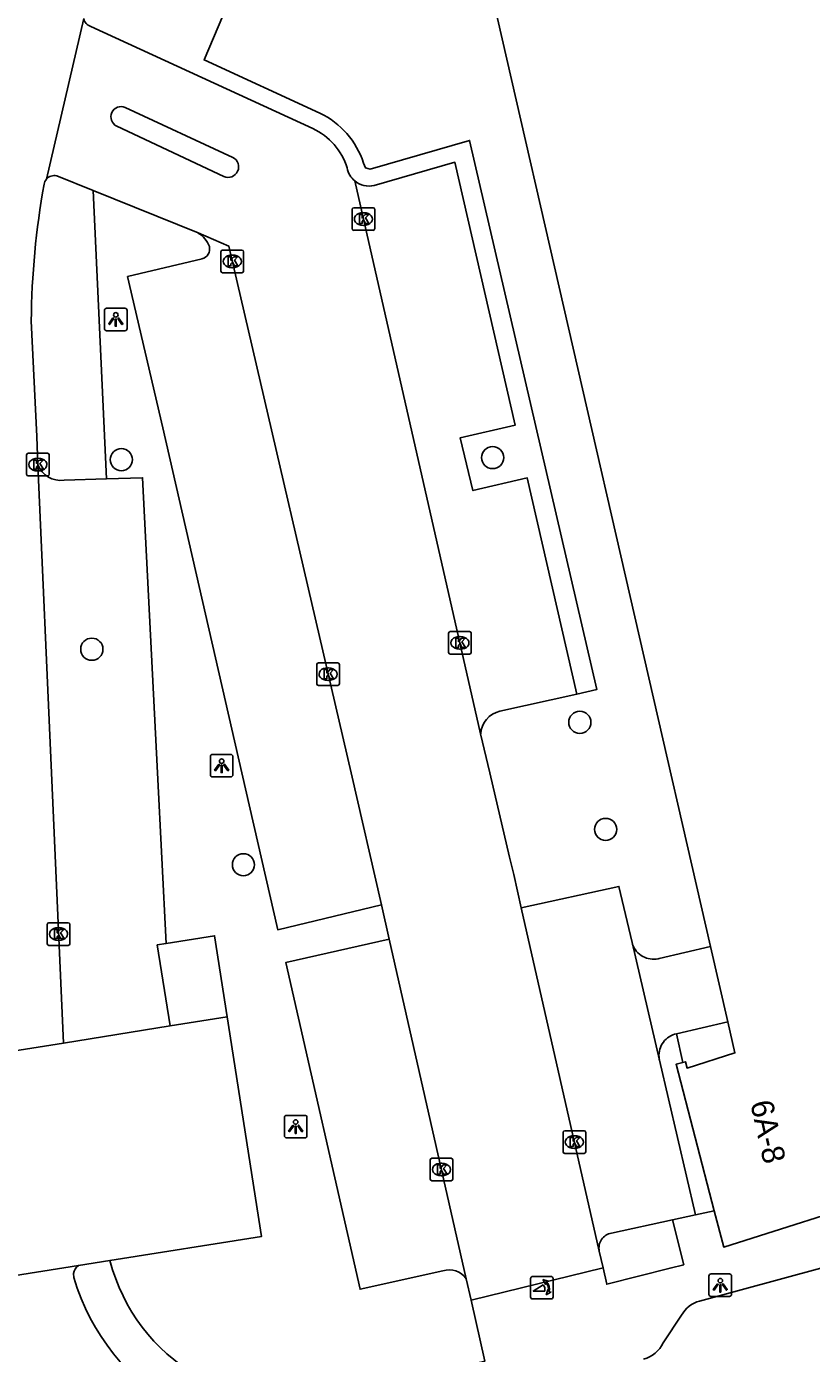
# Model space of a CAD drawing. Extents: x 160676 to 161153, y 383244 to 383713.
# Drawn here: x 160707.5 to 160742.2, y 383474.3 to 383533 of the extents above; entities that cross this region are included whole.
import ezdxf

# ---------------------------------------------------------------- set-up
doc = ezdxf.new("R2010")
doc.units = 0
for name, color, linetype in [('IMGEO_Boom', 7, 'Continuous'), ('IMGEO_Groenvoorziening', 7, 'Continuous'), ('IMGEO_Kolk', 7, 'Continuous'), ('IMGEO_Lichtpunt', 7, 'Continuous'), ('IMGEO_Pand', 7, 'Continuous'), ('IMGEO_Pand_nummerreeks', 7, 'Continuous'), ('IMGEO_Parkeervlak_open', 7, 'Continuous'), ('IMGEO_Poller', 7, 'Continuous'), ('IMGEO_Rijbaan_lokaal_open', 7, 'Continuous'), ('IMGEO_Voetpad_open', 7, 'Continuous')]:
    doc.layers.add(name, color=color, linetype=linetype)

msp = doc.modelspace()

# ---------------------------------------------------------------- linework, layer by layer
at = {"layer": 'IMGEO_Boom'}
for centre in [(160728.093, 383513.938), (160711.694, 383513.847), (160710.389, 383505.471), (160731.946, 383502.238), (160733.084, 383497.505), (160717.086, 383495.944)]:
    msp.add_circle(centre, 0.489, dxfattribs=at)
at = {"layer": 'IMGEO_Groenvoorziening'}
msp.add_lwpolyline([(160711.04, 383512.996), (160710.451, 383525.74)], dxfattribs=at)
at = {"layer": 'IMGEO_Kolk'}
for p, q in [((160721.96, 383524.981), (160722.812, 383524.981)), ((160721.885, 383524.055), (160721.885, 383524.907)), ((160722.373, 383524.761), (160722.398, 383524.761)), ((160722.886, 383524.907), (160722.886, 383524.055)), ((160722.812, 383523.981), (160721.96, 383523.981)), ((160722.396, 383524.201), (160722.371, 383524.201)), ((160716.092, 383522.182), (160716.092, 383523.034)), ((160716.167, 383523.108), (160717.019, 383523.108)), ((160716.58, 383522.888), (160716.605, 383522.888)), ((160717.093, 383523.034), (160717.093, 383522.182)), ((160717.019, 383522.108), (160716.167, 383522.108)), ((160716.603, 383522.328), (160716.578, 383522.328)), ((160707.505, 383513.202), (160707.505, 383514.054)), ((160707.58, 383514.128), (160708.432, 383514.128)), ((160707.993, 383513.908), (160708.018, 383513.908)), ((160708.506, 383514.054), (160708.506, 383513.202)), ((160708.016, 383513.348), (160707.991, 383513.348)), ((160708.432, 383513.128), (160707.58, 383513.128)), ((160726.222, 383506.251), (160727.074, 383506.251)), ((160726.147, 383505.325), (160726.147, 383506.177)), ((160726.635, 383506.031), (160726.66, 383506.031)), ((160727.148, 383506.177), (160727.148, 383505.325)), ((160727.074, 383505.251), (160726.222, 383505.251)), ((160726.658, 383505.471), (160726.633, 383505.471)), ((160720.326, 383503.941), (160720.326, 383504.793)), ((160720.401, 383504.867), (160721.253, 383504.867)), ((160720.814, 383504.647), (160720.839, 383504.647)), ((160721.327, 383504.793), (160721.327, 383503.941)), ((160721.253, 383503.867), (160720.401, 383503.867)), ((160720.837, 383504.087), (160720.812, 383504.087)), ((160708.418, 383492.454), (160708.418, 383493.306)), ((160708.493, 383493.38), (160709.345, 383493.38)), ((160709.419, 383493.306), (160709.419, 383492.454)), ((160708.906, 383493.16), (160708.931, 383493.16)), ((160709.345, 383492.38), (160708.493, 383492.38)), ((160708.929, 383492.6), (160708.904, 383492.6)), ((160731.204, 383483.263), (160731.204, 383484.115)), ((160731.279, 383484.189), (160732.131, 383484.189)), ((160731.692, 383483.969), (160731.717, 383483.969)), ((160732.205, 383484.115), (160732.205, 383483.263)), ((160731.715, 383483.409), (160731.69, 383483.409)), ((160725.334, 383482.051), (160725.334, 383482.903)), ((160725.409, 383482.977), (160726.261, 383482.977)), ((160725.822, 383482.757), (160725.847, 383482.757)), ((160726.335, 383482.903), (160726.335, 383482.051)), ((160732.131, 383483.189), (160731.279, 383483.189)), ((160725.845, 383482.197), (160725.82, 383482.197)), ((160726.261, 383481.977), (160725.409, 383481.977))]:
    msp.add_line(p, q, dxfattribs=at)
for points in [[(160721.96, 383524.981), (160722.812, 383524.981)], [(160721.885, 383524.055), (160721.885, 383524.907)], [(160722.206, 383524.681), (160722.329, 383524.681), (160722.329, 383524.53), (160722.459, 383524.681), (160722.623, 383524.681), (160722.477, 383524.53), (160722.63, 383524.281), (160722.478, 383524.281), (160722.393, 383524.445), (160722.329, 383524.378), (160722.329, 383524.281), (160722.206, 383524.281), (160722.206, 383524.681)], [(160722.886, 383524.907), (160722.886, 383524.055)], [(160722.812, 383523.981), (160721.96, 383523.981)], [(160716.092, 383522.182), (160716.092, 383523.034)], [(160716.167, 383523.108), (160717.019, 383523.108)], [(160716.413, 383522.808), (160716.536, 383522.808), (160716.536, 383522.657), (160716.666, 383522.808), (160716.83, 383522.808), (160716.684, 383522.657), (160716.837, 383522.408), (160716.685, 383522.408), (160716.6, 383522.572), (160716.536, 383522.505), (160716.536, 383522.408), (160716.413, 383522.408), (160716.413, 383522.808)], [(160717.093, 383523.034), (160717.093, 383522.182)], [(160717.019, 383522.108), (160716.167, 383522.108)], [(160707.505, 383513.202), (160707.505, 383514.054)], [(160707.58, 383514.128), (160708.432, 383514.128)], [(160707.826, 383513.828), (160707.949, 383513.828), (160707.949, 383513.677), (160708.079, 383513.828), (160708.243, 383513.828), (160708.097, 383513.677), (160708.25, 383513.428), (160708.098, 383513.428), (160708.013, 383513.592), (160707.949, 383513.525), (160707.949, 383513.428), (160707.826, 383513.428), (160707.826, 383513.828)], [(160708.506, 383514.054), (160708.506, 383513.202)], [(160708.432, 383513.128), (160707.58, 383513.128)], [(160726.222, 383506.251), (160727.074, 383506.251)], [(160726.147, 383505.325), (160726.147, 383506.177)], [(160726.468, 383505.951), (160726.591, 383505.951), (160726.591, 383505.8), (160726.721, 383505.951), (160726.885, 383505.951), (160726.739, 383505.8), (160726.892, 383505.551), (160726.74, 383505.551), (160726.655, 383505.715), (160726.591, 383505.648), (160726.591, 383505.551), (160726.468, 383505.551), (160726.468, 383505.951)], [(160727.148, 383506.177), (160727.148, 383505.325)], [(160727.074, 383505.251), (160726.222, 383505.251)], [(160720.326, 383503.941), (160720.326, 383504.793)], [(160720.401, 383504.867), (160721.253, 383504.867)], [(160720.647, 383504.567), (160720.77, 383504.567), (160720.77, 383504.416), (160720.9, 383504.567), (160721.064, 383504.567), (160720.918, 383504.416), (160721.071, 383504.167), (160720.919, 383504.167), (160720.834, 383504.331), (160720.77, 383504.264), (160720.77, 383504.167), (160720.647, 383504.167), (160720.647, 383504.567)], [(160721.327, 383504.793), (160721.327, 383503.941)], [(160721.253, 383503.867), (160720.401, 383503.867)], [(160708.418, 383492.454), (160708.418, 383493.306)], [(160708.493, 383493.38), (160709.345, 383493.38)], [(160709.419, 383493.306), (160709.419, 383492.454)], [(160708.739, 383493.08), (160708.862, 383493.08), (160708.862, 383492.929), (160708.992, 383493.08), (160709.156, 383493.08), (160709.01, 383492.929), (160709.163, 383492.68), (160709.011, 383492.68), (160708.926, 383492.844), (160708.862, 383492.777), (160708.862, 383492.68), (160708.739, 383492.68), (160708.739, 383493.08)], [(160709.345, 383492.38), (160708.493, 383492.38)], [(160731.204, 383483.263), (160731.204, 383484.115)], [(160731.279, 383484.189), (160732.131, 383484.189)], [(160732.205, 383484.115), (160732.205, 383483.263)], [(160731.525, 383483.889), (160731.648, 383483.889), (160731.648, 383483.738), (160731.778, 383483.889), (160731.942, 383483.889), (160731.796, 383483.738), (160731.949, 383483.489), (160731.797, 383483.489), (160731.712, 383483.653), (160731.648, 383483.586), (160731.648, 383483.489), (160731.525, 383483.489), (160731.525, 383483.889)], [(160725.334, 383482.051), (160725.334, 383482.903)], [(160725.409, 383482.977), (160726.261, 383482.977)], [(160726.335, 383482.903), (160726.335, 383482.051)], [(160732.131, 383483.189), (160731.279, 383483.189)], [(160725.655, 383482.677), (160725.778, 383482.677), (160725.778, 383482.526), (160725.908, 383482.677), (160726.072, 383482.677), (160725.926, 383482.526), (160726.079, 383482.277), (160725.927, 383482.277), (160725.842, 383482.441), (160725.778, 383482.374), (160725.778, 383482.277), (160725.655, 383482.277), (160725.655, 383482.677)], [(160726.261, 383481.977), (160725.409, 383481.977)]]:
    msp.add_lwpolyline(points, dxfattribs=at)
for centre, start, end in [((160721.962, 383524.905), 91.55205, 178.44795), ((160721.962, 383524.905), 91.55205, 178.44795), ((160722.81, 383524.905), 1.55205, 88.44795), ((160722.81, 383524.905), 1.55205, 88.44795), ((160721.962, 383524.057), 181.55205, 268.44795), ((160721.962, 383524.057), 181.55205, 268.44795), ((160722.81, 383524.057), 271.55205, 358.44795), ((160722.81, 383524.057), 271.55205, 358.44795), ((160716.169, 383523.032), 91.55205, 178.44795), ((160716.169, 383523.032), 91.55205, 178.44795), ((160717.017, 383523.032), 1.55205, 88.44795), ((160717.017, 383523.032), 1.55205, 88.44795), ((160716.169, 383522.184), 181.55205, 268.44795), ((160716.169, 383522.184), 181.55205, 268.44795), ((160717.017, 383522.184), 271.55205, 358.44795), ((160717.017, 383522.184), 271.55205, 358.44795), ((160707.582, 383514.052), 91.55205, 178.44795), ((160707.582, 383514.052), 91.55205, 178.44795), ((160708.43, 383514.052), 1.55205, 88.44795), ((160708.43, 383514.052), 1.55205, 88.44795), ((160707.582, 383513.204), 181.55205, 268.44795), ((160707.582, 383513.204), 181.55205, 268.44795), ((160708.43, 383513.204), 271.55205, 358.44795), ((160708.43, 383513.204), 271.55205, 358.44795), ((160726.224, 383506.175), 91.55205, 178.44795), ((160726.224, 383506.175), 91.55205, 178.44795), ((160727.072, 383506.175), 1.55205, 88.44795), ((160727.072, 383506.175), 1.55205, 88.44795), ((160726.224, 383505.327), 181.55205, 268.44795), ((160726.224, 383505.327), 181.55205, 268.44795), ((160727.072, 383505.327), 271.55205, 358.44795), ((160727.072, 383505.327), 271.55205, 358.44795), ((160720.403, 383504.791), 91.55205, 178.44795), ((160720.403, 383504.791), 91.55205, 178.44795), ((160721.251, 383504.791), 1.55205, 88.44795), ((160721.251, 383504.791), 1.55205, 88.44795), ((160720.403, 383503.943), 181.55205, 268.44795), ((160720.403, 383503.943), 181.55205, 268.44795), ((160721.251, 383503.943), 271.55205, 358.44795), ((160721.251, 383503.943), 271.55205, 358.44795), ((160708.495, 383493.304), 91.55205, 178.44795), ((160708.495, 383493.304), 91.55205, 178.44795), ((160709.343, 383493.304), 1.55205, 88.44795), ((160709.343, 383493.304), 1.55205, 88.44795), ((160708.495, 383492.456), 181.55205, 268.44795), ((160708.495, 383492.456), 181.55205, 268.44795), ((160709.343, 383492.456), 271.55205, 358.44795), ((160709.343, 383492.456), 271.55205, 358.44795), ((160731.281, 383484.113), 91.55205, 178.44795), ((160731.281, 383484.113), 91.55205, 178.44795), ((160732.129, 383484.113), 1.55205, 88.44795), ((160732.129, 383484.113), 1.55205, 88.44795), ((160725.411, 383482.901), 91.55205, 178.44795), ((160725.411, 383482.901), 91.55205, 178.44795), ((160726.259, 383482.901), 1.55205, 88.44795), ((160726.259, 383482.901), 1.55205, 88.44795), ((160731.281, 383483.265), 181.55205, 268.44795), ((160731.281, 383483.265), 181.55205, 268.44795), ((160732.129, 383483.265), 271.55205, 358.44795), ((160732.129, 383483.265), 271.55205, 358.44795), ((160725.411, 383482.053), 181.55205, 268.44795), ((160725.411, 383482.053), 181.55205, 268.44795), ((160726.259, 383482.053), 271.55205, 358.44795), ((160726.259, 383482.053), 271.55205, 358.44795)]:
    msp.add_arc(centre, 0.0765, start, end, dxfattribs=at)
for centre, major_axis, ratio, start_param, end_param in [((160722.372, 383524.481), (-0.387, 0.002), 0.722429, 4.712389, 7.853982), ((160722.397, 383524.481), (-0.39, 0.002), 0.717154, 1.570796, 4.712389), ((160716.579, 383522.608), (-0.387, 0.002), 0.722429, 4.712389, 7.853982), ((160716.604, 383522.608), (-0.39, 0.002), 0.717154, 1.570796, 4.712389), ((160707.992, 383513.628), (-0.387, 0.002), 0.722429, 4.712389, 7.853982), ((160708.017, 383513.628), (-0.39, 0.002), 0.717154, 1.570796, 4.712389), ((160726.634, 383505.751), (-0.387, 0.002), 0.722429, 4.712389, 7.853982), ((160726.659, 383505.751), (-0.39, 0.002), 0.717154, 1.570796, 4.712389), ((160720.813, 383504.367), (-0.387, 0.002), 0.722429, 4.712389, 7.853982), ((160720.838, 383504.367), (-0.39, 0.002), 0.717154, 1.570796, 4.712389), ((160708.905, 383492.88), (-0.387, 0.002), 0.722429, 4.712389, 7.853982), ((160708.93, 383492.88), (-0.39, 0.002), 0.717154, 1.570796, 4.712389), ((160731.691, 383483.689), (-0.387, 0.002), 0.722429, 4.712389, 7.853982), ((160731.716, 383483.689), (-0.39, 0.002), 0.717154, 1.570796, 4.712389), ((160725.821, 383482.477), (-0.387, 0.002), 0.722429, 4.712389, 7.853982), ((160725.846, 383482.477), (-0.39, 0.002), 0.717154, 1.570796, 4.712389)]:
    msp.add_ellipse(centre, major_axis=major_axis, ratio=ratio, start_param=start_param, end_param=end_param, dxfattribs=at)
at = {"layer": 'IMGEO_Lichtpunt'}
for p, q in [((160710.948, 383520.445), (160710.948, 383519.638)), ((160710.948, 383520.445), (160710.948, 383519.638)), ((160711.85, 383520.54), (160711.042, 383520.54)), ((160711.85, 383520.54), (160711.042, 383520.54)), ((160711.944, 383519.638), (160711.944, 383520.445)), ((160711.944, 383519.638), (160711.944, 383520.445)), ((160711.042, 383519.544), (160711.85, 383519.544)), ((160711.042, 383519.544), (160711.85, 383519.544)), ((160715.625, 383500.727), (160715.625, 383499.92)), ((160715.625, 383500.727), (160715.625, 383499.92)), ((160716.527, 383500.822), (160715.719, 383500.822)), ((160716.527, 383500.822), (160715.719, 383500.822)), ((160716.621, 383499.92), (160716.621, 383500.727)), ((160716.621, 383499.92), (160716.621, 383500.727)), ((160715.719, 383499.826), (160716.527, 383499.826)), ((160715.719, 383499.826), (160716.527, 383499.826)), ((160718.896, 383484.775), (160718.896, 383483.968)), ((160718.896, 383484.775), (160718.896, 383483.968)), ((160719.798, 383484.87), (160718.99, 383484.87)), ((160719.798, 383484.87), (160718.99, 383484.87)), ((160719.892, 383483.968), (160719.892, 383484.775)), ((160719.892, 383483.968), (160719.892, 383484.775)), ((160718.99, 383483.874), (160719.798, 383483.874)), ((160718.99, 383483.874), (160719.798, 383483.874)), ((160737.65, 383477.767), (160737.65, 383476.96)), ((160737.65, 383477.767), (160737.65, 383476.96)), ((160738.552, 383477.862), (160737.744, 383477.862)), ((160738.552, 383477.862), (160737.744, 383477.862)), ((160738.646, 383476.96), (160738.646, 383477.767)), ((160738.646, 383476.96), (160738.646, 383477.767)), ((160737.744, 383476.866), (160738.552, 383476.866)), ((160737.744, 383476.866), (160738.552, 383476.866))]:
    msp.add_line(p, q, dxfattribs=at)
for points in [[(160711.322, 383520.109), (160711.361, 383520.081), (160711.173, 383519.819), (160711.135, 383519.846), (160711.322, 383520.109)], [(160711.424, 383520.061), (160711.471, 383520.061), (160711.471, 383519.739), (160711.424, 383519.739), (160711.424, 383520.061)], [(160711.534, 383520.081), (160711.572, 383520.108), (160711.759, 383519.846), (160711.72, 383519.818), (160711.534, 383520.081)], [(160715.999, 383500.391), (160716.038, 383500.363), (160715.85, 383500.101), (160715.812, 383500.128), (160715.999, 383500.391)], [(160716.101, 383500.343), (160716.148, 383500.343), (160716.148, 383500.021), (160716.101, 383500.021), (160716.101, 383500.343)], [(160716.211, 383500.363), (160716.249, 383500.39), (160716.436, 383500.128), (160716.397, 383500.1), (160716.211, 383500.363)], [(160719.27, 383484.439), (160719.309, 383484.411), (160719.121, 383484.149), (160719.083, 383484.176), (160719.27, 383484.439)], [(160719.372, 383484.391), (160719.419, 383484.391), (160719.419, 383484.069), (160719.372, 383484.069), (160719.372, 383484.391)], [(160719.482, 383484.411), (160719.52, 383484.438), (160719.707, 383484.176), (160719.668, 383484.148), (160719.482, 383484.411)], [(160738.024, 383477.431), (160738.063, 383477.403), (160737.875, 383477.141), (160737.837, 383477.168), (160738.024, 383477.431)], [(160738.126, 383477.383), (160738.173, 383477.383), (160738.173, 383477.061), (160738.126, 383477.061), (160738.126, 383477.383)], [(160738.236, 383477.403), (160738.274, 383477.43), (160738.461, 383477.168), (160738.422, 383477.14), (160738.236, 383477.403)]]:
    msp.add_lwpolyline(points, dxfattribs=at)
for centre in [(160711.447, 383520.243), (160716.124, 383500.525), (160719.395, 383484.573), (160738.149, 383477.565)]:
    msp.add_circle(centre, 0.0994, dxfattribs=at)
for centre, start, end in [((160711.042, 383520.445), 90, 180), ((160711.042, 383520.445), 90, 180), ((160711.85, 383520.445), 0, 90), ((160711.85, 383520.445), 0, 90), ((160711.042, 383519.638), 180, 270), ((160711.042, 383519.638), 180, 270), ((160711.85, 383519.638), 270, 0), ((160711.85, 383519.638), 270, 360), ((160715.719, 383500.727), 90, 180), ((160715.719, 383500.727), 90, 180), ((160716.527, 383500.727), 0, 90), ((160716.527, 383500.727), 0, 90), ((160715.719, 383499.92), 180, 270), ((160715.719, 383499.92), 180, 270), ((160716.527, 383499.92), 270, 0), ((160716.527, 383499.92), 270, 360), ((160718.99, 383484.775), 90, 180), ((160718.99, 383484.775), 90, 180), ((160719.798, 383484.775), 0, 90), ((160719.798, 383484.775), 0, 90), ((160718.99, 383483.968), 180, 270), ((160718.99, 383483.968), 180, 270), ((160719.798, 383483.968), 270, 0), ((160719.798, 383483.968), 270, 360), ((160737.744, 383477.767), 90, 180), ((160737.744, 383477.767), 90, 180), ((160738.552, 383477.767), 0, 90), ((160738.552, 383477.767), 0, 90), ((160737.744, 383476.96), 180, 270), ((160737.744, 383476.96), 180, 270), ((160738.552, 383476.96), 270, 0), ((160738.552, 383476.96), 270, 360)]:
    msp.add_arc(centre, 0.0946, start, end, dxfattribs=at)
at = {"layer": 'IMGEO_Pand'}
for points in [[(160737.721, 383492.328), (160725.173, 383547.028)], [(160789.904, 383497.87), (160767.23, 383488.234), (160738.303, 383479.05), (160737.884, 383480.656)], [(160716.372, 383489.219), (160715.813, 383492.805), (160713.669, 383492.461)], [(160713.669, 383492.461), (160713.279, 383492.399), (160713.852, 383488.823)], [(160737.721, 383492.328), (160738.483, 383489.005)], [(160716.372, 383489.219), (160717.884, 383479.519), (160711.188, 383478.453)], [(160713.852, 383488.823), (160716.372, 383489.219)], [(160709.132, 383488.067), (160713.852, 383488.823)], [(160738.483, 383489.005), (160738.799, 383487.63), (160736.683, 383486.957), (160736.61, 383487.238), (160736.489, 383487.206)], [(160702.884, 383487.072), (160709.132, 383488.067)], [(160736.489, 383487.206), (160736.194, 383487.129), (160737.884, 383480.656)], [(160704.503, 383477.389), (160709.795, 383478.231)], [(160711.188, 383478.453), (160709.795, 383478.231)]]:
    msp.add_lwpolyline(points, dxfattribs=at)
at = {"layer": 'IMGEO_Parkeervlak_open'}
for points in [[(160723.192, 383494.173), (160718.603, 383493.071), (160717.015, 383500), (160713.519, 383515.256), (160711.968, 383521.939), (160715.256, 383522.716)], [(160709.166, 383512.934), (160711.04, 383512.996)], [(160713.669, 383492.461), (160713.289, 383500), (160712.633, 383513.049), (160711.04, 383512.996)], [(160731.814, 383503.489), (160728.417, 383502.725)], [(160729.35, 383494.038), (160733.671, 383494.988), (160734.251, 383492.503)], [(160725.9, 383478.001), (160722.239, 383477.188), (160718.953, 383491.622), (160723.529, 383492.661)], [(160733.347, 383479.665), (160736.046, 383480.255)]]:
    msp.add_lwpolyline(points, dxfattribs=at)
for centre, radius, start, end in [((160714.542, 383522.908), 1.096, 18.76188, 60.54904), ((160715.142, 383523.152), 0.451, 284.59568, 13.94174), ((160709.027, 383514.02), 1.094, 201.41347, 277.30147), ((160728.654, 383501.661), 1.09, 102.53469, 176.71632), ((160733.463, 383479.003), 0.673, 99.92649, 191.53992), ((160726.173, 383477.124), 0.918, 34.85336, 107.30876)]:
    msp.add_arc(centre, radius, start, end, dxfattribs=at)
at = {"layer": 'IMGEO_Poller'}
for p, q in [((160729.768, 383477.656), (160729.768, 383476.849)), ((160729.768, 383477.656), (160729.768, 383476.849)), ((160730.67, 383477.751), (160729.862, 383477.751)), ((160730.67, 383477.751), (160729.862, 383477.751)), ((160730.764, 383476.849), (160730.764, 383477.656)), ((160730.764, 383476.849), (160730.764, 383477.656)), ((160729.862, 383476.754), (160730.67, 383476.754)), ((160729.862, 383476.754), (160730.67, 383476.754))]:
    msp.add_line(p, q, dxfattribs=at)
for points in [[(160730.447, 383477.48), (160730.435, 383477.407), (160730.31, 383477.612)], [(160730.31, 383477.612), (160730.541, 383477.546), (160730.47, 383477.514)], [(160730.403, 383477.107), (160729.89, 383477.107), (160730.32, 383477.382)], [(160730.463, 383476.935), (160730.529, 383477.166), (160730.559, 383477.098)], [(160730.595, 383477.071), (160730.667, 383477.06), (160730.463, 383476.935)]]:
    msp.add_lwpolyline(points, dxfattribs=at)
for centre, radius, start, end in [((160729.862, 383477.656), 0.0946, 90, 180), ((160729.862, 383477.656), 0.0946, 90, 180), ((160730.089, 383477.167), 0.476, 351.75274, 41.16905), ((160730.089, 383477.167), 0.516, 349.35686, 42.29123), ((160730.67, 383477.656), 0.0946, 0, 90), ((160730.67, 383477.656), 0.0946, 0, 90), ((160730.075, 383477.157), 0.332, 351.32473, 42.4854), ((160729.862, 383476.849), 0.0946, 180, 270), ((160729.862, 383476.849), 0.0946, 180, 270), ((160730.67, 383476.849), 0.0946, 270, 0), ((160730.67, 383476.849), 0.0946, 270, 0)]:
    msp.add_arc(centre, radius, start, end, dxfattribs=at)
at = {"layer": 'IMGEO_Rijbaan_lokaal_open'}
for points in [[(160708.388, 383526.243), (160710.033, 383533.347)], [(160710.34, 383532.987), (160720.149, 383528.479)], [(160716.618, 383527.201), (160711.867, 383529.41)], [(160711.49, 383528.589), (160716.224, 383526.362)], [(160710.451, 383525.74), (160708.839, 383526.394)], [(160722.003, 383526.166), (160727.565, 383501.723)], [(160715.081, 383523.863), (160710.451, 383525.74)], [(160723.192, 383494.173), (160721.84, 383500), (160716.435, 383523.285), (160715.081, 383523.863)], [(160708.008, 383513.62), (160707.953, 383514.866), (160707.714, 383519.975)], [(160709.132, 383488.067), (160708.607, 383500), (160708.008, 383513.62)], [(160727.565, 383501.723), (160727.97, 383500), (160728.843, 383496.285), (160729.026, 383495.511), (160729.35, 383494.038)], [(160723.529, 383492.661), (160723.192, 383494.173)], [(160729.35, 383494.038), (160732.804, 383478.868)], [(160726.927, 383477.649), (160723.529, 383492.661)], [(160732.804, 383478.868), (160732.97, 383478.135)], [(160732.97, 383478.135), (160727.142, 383476.7)], [(160727.142, 383476.7), (160726.927, 383477.649)]]:
    msp.add_lwpolyline(points, dxfattribs=at)
for centre, radius, start, end in [((160710.493, 383533.428), 0.467, 189.99302, 250.92059), ((160711.685, 383528.996), 0.452, 66.30946, 244.36174), ((160718.922, 383525.876), 2.878, 17.38868, 64.7547), ((160716.411, 383526.786), 0.464, 246.2739, 63.41597), ((160722.632, 383526.919), 0.981, 190.75312, 230.13403), ((160708.734, 383525.941), 0.459, 138.82694, 170.30569), ((160708.74, 383525.941), 0.464, 77.67999, 139.34229), ((160743.748, 383519.642), 36.035, 169.80878, 179.47076)]:
    msp.add_arc(centre, radius, start, end, dxfattribs=at)
at = {"layer": 'IMGEO_Voetpad_open'}
for points in [[(160720.463, 383529.159), (160715.345, 383531.511), (160716.176, 383533.454)], [(160731.814, 383503.489), (160732.691, 383503.686), (160727.075, 383527.958), (160722.684, 383526.688), (160722.485, 383526.74), (160722.385, 383526.955)], [(160722.863, 383525.96), (160726.428, 383526.991), (160729.09, 383515.375), (160726.66, 383514.813), (160727.226, 383512.481), (160729.626, 383513.036), (160731.814, 383503.489)], [(160737.233, 383476.662), (160742.593, 383478.11), (160745.398, 383478.868), (160748.941, 383479.839), (160752.477, 383480.836), (160758.455, 383482.574), (160764.417, 383484.369), (160770.863, 383486.368), (160777.275, 383488.471), (160782.936, 383490.488), (160788.554, 383492.621), (160789.861, 383493.144), (160795.666, 383495.465), (160795.689, 383495.474), (160802.758, 383498.486), (160804.362, 383499.229), (160805.953, 383500)], [(160734.251, 383492.503), (160735.463, 383487.305)], [(160734.251, 383492.503), (160734.277, 383492.419), (160734.311, 383492.337), (160734.352, 383492.259), (160734.399, 383492.185), (160734.453, 383492.116), (160734.513, 383492.051), (160734.579, 383491.992), (160734.649, 383491.939), (160734.724, 383491.893), (160734.803, 383491.854), (160734.885, 383491.822), (160734.97, 383491.797), (160735.056, 383491.78), (160735.144, 383491.77), (160735.232, 383491.769), (160735.32, 383491.775), (160735.407, 383491.79), (160735.443, 383491.798), (160737.721, 383492.328)], [(160738.483, 383489.005), (160736.217, 383488.477)], [(160736.217, 383488.477), (160736.132, 383488.455), (160736.049, 383488.425), (160735.969, 383488.387), (160735.893, 383488.343), (160735.821, 383488.292), (160735.754, 383488.235), (160735.692, 383488.172), (160735.637, 383488.104), (160735.587, 383488.031), (160735.544, 383487.954), (160735.508, 383487.874), (160735.48, 383487.79), (160735.459, 383487.705), (160735.446, 383487.618), (160735.441, 383487.53), (160735.443, 383487.442), (160735.454, 383487.354), (160735.463, 383487.305)], [(160736.489, 383487.206), (160736.217, 383488.477)], [(160735.463, 383487.305), (160737.055, 383480.475)], [(160737.055, 383480.475), (160736.046, 383480.255)], [(160737.884, 383480.656), (160737.055, 383480.475)], [(160736.046, 383480.255), (160736.535, 383478.268), (160735.932, 383478.12), (160733.136, 383477.406), (160732.97, 383478.135)], [(160709.581, 383477.877), (160709.589, 383477.697)], [(160727.142, 383476.7), (160727.751, 383474.009), (160721.224, 383472.437)], [(160735.632, 383474.811), (160736.437, 383476.035)]]:
    msp.add_lwpolyline(points, dxfattribs=at)
for centre, radius, start, end in [((160718.896, 383525.852), 3.66, 17.5402, 64.63996), ((160722.638, 383526.919), 0.985, 229.86527, 283.19367), ((160710.088, 383477.812), 0.511, 124.99096, 172.70145), ((160719.274, 383480.563), 8.356, 194.6233, 283.49621), ((160719.238, 383480.603), 10.077, 196.76131, 282.08384), ((160737.559, 383475.43), 1.274, 104.80341, 151.65078), ((160734.377, 383475.45), 1.408, 285.77633, 333.00257)]:
    msp.add_arc(centre, radius, start, end, dxfattribs=at)

# ---------------------------------------------------------------- texts
at = {"layer": 'IMGEO_Pand_nummerreeks'}
msp.add_text('6A-8', height=1, rotation=282.54184, dxfattribs=at).set_placement((160739.467, 383485.423))

doc.saveas('drawing.dxf')
